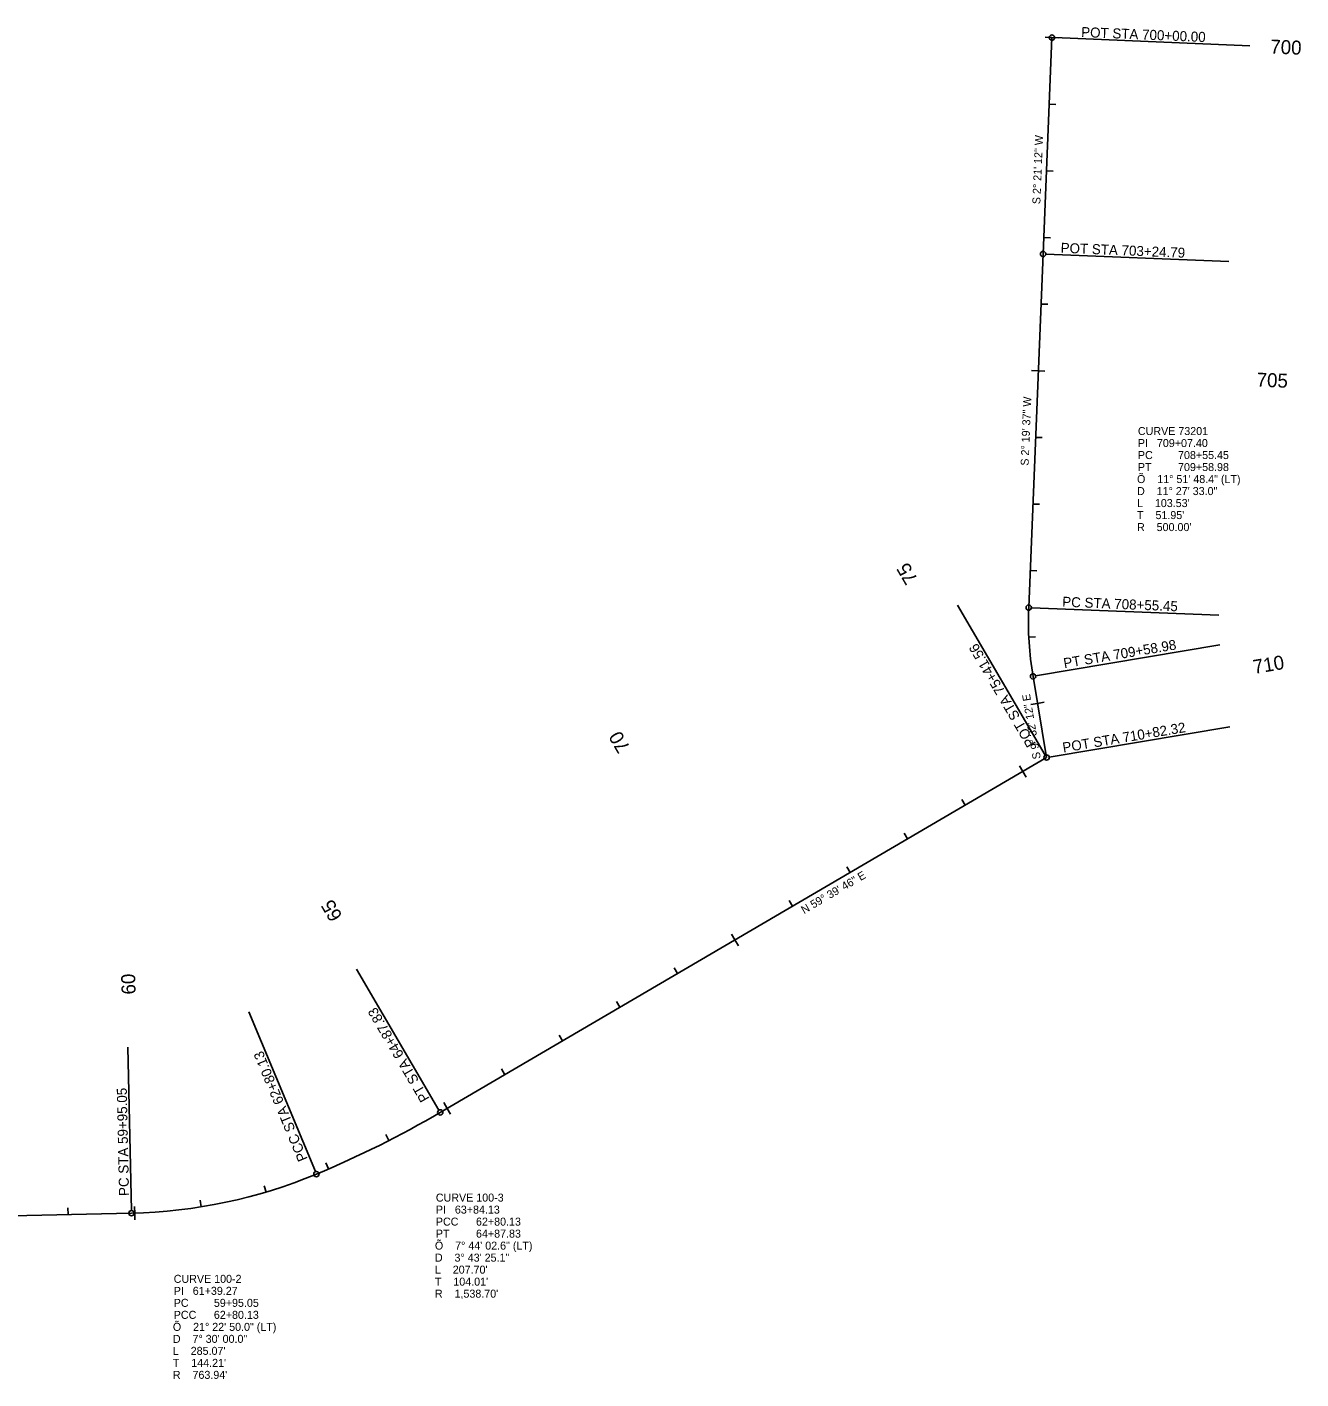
# Model space of a CAD drawing. Extents: x 2819977 to 2827606, y 113942 to 150283.
# Drawn here: x 2821906 to 2823816, y 131900 to 133927 of the extents above; entities that cross this region are included whole.
import ezdxf

# ---------------------------------------------------------------- set-up
doc = ezdxf.new("R2010")
doc.units = 0
for name, color, linetype in [('Level 63', 7, 'Continuous'), ('Roadway-Safety', 7, 'Continuous'), ('Roadway-Signs', 7, 'Continuous'), ('Roadway-Walls', 7, 'Continuous'), ('Utility-Power', 7, 'Continuous')]:
    doc.layers.add(name, color=color, linetype=linetype)

msp = doc.modelspace()

# ---------------------------------------------------------------- linework, layer by layer
at = {"layer": 'Level 63'}
msp.add_circle((2823434.8, 132831.9), 4, dxfattribs=at)
at = {"layer": 'Roadway-Safety'}
for p, q in [((2823446.8, 133911.3), (2823739.8, 133899.2)), ((2823433.4, 133586.7), (2823708, 133575.5)), ((2823432.8, 132835.4), (2823301.3, 133060.2)), ((2823411.9, 133056.5), (2823693.2, 133045.1)), ((2823418.3, 132954.2), (2823694.5, 133000.6)), ((2823438.8, 132832.6), (2823709.7, 132878.1)), ((2822523.4, 132303.1), (2822399.8, 132514.4)), ((2822338.1, 132210.9), (2822238.2, 132450.7)), ((2822062.2, 132152.7), (2822057, 132397.4))]:
    msp.add_line(p, q, dxfattribs=at)
at = {"layer": 'Utility-Power'}
for p, q in [((2823442.8, 133911.4), (2823429.5, 133586.9)), ((2823442.8, 133911.4), (2823432.8, 133911.8)), ((2823442.8, 133911.4), (2823452.8, 133911)), ((2823438.7, 133811.5), (2823448.7, 133811.1)), ((2823434.6, 133711.6), (2823444.6, 133711.2)), ((2823430.5, 133611.7), (2823440.5, 133611.3)), ((2823429.5, 133586.9), (2823407.9, 133056.7)), ((2823426.4, 133511.8), (2823436.4, 133511.4)), ((2823422.3, 133411.8), (2823412.3, 133412.2)), ((2823422.3, 133411.8), (2823432.3, 133411.4)), ((2823418.3, 133311.9), (2823428.3, 133311.5)), ((2823414.2, 133212), (2823424.2, 133211.6)), ((2823410.2, 133112.1), (2823420.1, 133111.7)), ((2823408.1, 133012.2), (2823418.1, 133012.6)), ((2823414.4, 132953.5), (2823434.8, 132831.9)), ((2823421.2, 132913.1), (2823411.3, 132911.4)), ((2823421.2, 132913.1), (2823431.1, 132914.7)), ((2822525.4, 132299.7), (2823434.8, 132831.9)), ((2823399, 132810.9), (2823393.9, 132819.6)), ((2823399, 132810.9), (2823404, 132802.3)), ((2823312.7, 132760.4), (2823307.6, 132769)), ((2823226.4, 132709.9), (2823221.3, 132718.5)), ((2823140, 132659.4), (2823135, 132668)), ((2823053.7, 132608.9), (2823048.7, 132617.5)), ((2822967.4, 132558.4), (2822962.4, 132567)), ((2822967.4, 132558.4), (2822972.5, 132549.7)), ((2822881.1, 132507.9), (2822876.1, 132516.5)), ((2822794.8, 132457.4), (2822789.8, 132466)), ((2822708.5, 132406.9), (2822703.5, 132415.5)), ((2822622.2, 132356.3), (2822617.2, 132365)), ((2822535.9, 132305.8), (2822530.8, 132314.5)), ((2822535.9, 132305.8), (2822541, 132297.2)), ((2822448.4, 132257.5), (2822443.8, 132266.4)), ((2822357.9, 132214.9), (2822353.9, 132224.1)), ((2822264.2, 132180.3), (2822261.3, 132189.9)), ((2822166.7, 132158.1), (2822165.2, 132168)), ((2821496.2, 132136.6), (2822062.3, 132148.7)), ((2821967.3, 132146.6), (2821967, 132156.6)), ((2822067.2, 132148.8), (2822067, 132158.8)), ((2822067.2, 132148.8), (2822067.5, 132138.8))]:
    msp.add_line(p, q, dxfattribs=at)
for centre in [(2823442.8, 133911.4), (2823429.5, 133586.9), (2823407.9, 133056.7), (2823414.4, 132953.5), (2823434.8, 132831.9), (2822525.4, 132299.7), (2822339.6, 132207.2), (2822062.3, 132148.7)]:
    msp.add_circle(centre, 4, dxfattribs=at)
for centre, radius, start, end in [((2823907.5, 133036.4), 500, 177.6731, 189.5366), ((2821748.2, 133627.7), 1538.7, 292.6032, 300.3373), ((2822046, 132912.4), 763.9, 271.2227, 292.6032)]:
    msp.add_arc(centre, radius, start, end, dxfattribs=at)

# ---------------------------------------------------------------- texts
at = {"layer": 'Roadway-Safety'}
for s, rotation, p in [('POT STA 700+00.00', 357.6466, (2823486.4, 133912.3)), ('POT STA 703+24.79', 357.6466, (2823455.6, 133588.8)), ('PC STA 708+55.45', 357.6731, (2823458, 133058.1)), ('POT STA 75+41.56', 120.3373, (2823419.1, 132852.8)), ('PT STA 709+58.98', 9.5366, (2823461.4, 132965.7)), ('POT STA 710+82.32', 9.5366, (2823460, 132839.2)), ('PT STA 64+87.83', 120.3373, (2822509.7, 132320.6)), ('PCC STA 62+80.13', 112.6032, (2822326.8, 132230)), ('PC STA 59+95.05', 91.2227, (2822058.7, 132174.6))]:
    msp.add_text(s, height=15, rotation=rotation, dxfattribs=at).set_placement(p)
at = {"layer": 'Roadway-Signs'}
for s, rotation, p in [('S 2%%d 21\' 12" W', 87.6466, (2823425.3, 133661.4)), ('S 2%%d 19\' 37" W', 87.6731, (2823407.7, 133269.3)), ('S 9%%d 32\' 12" E', 99.5366, (2823426.1, 132830.4)), ('N 59%%d 39\' 46" E', 30.3373, (2823071, 132597))]:
    msp.add_text(s, height=12, rotation=rotation, dxfattribs=at).set_placement(p)
at = {"layer": 'Roadway-Walls'}
for s, p in [('CURVE 73201', (2823571.7, 133315.4)), ('PI   709+07.40', (2823571.7, 133297.4)), ('PC', (2823571.7, 133279.4)), ('708+55.45', (2823631.9, 133279.4)), ('PT', (2823571.7, 133261.4)), ('709+58.98', (2823631.9, 133261.4)), ('Õ    11%%d 51\' 48.4" (LT)', (2823570.4, 133243.4)), ('D    11%%d 27\' 33.0"', (2823570.4, 133225.4)), ("T    51.95'", (2823570.4, 133189.4)), ("L    103.53'", (2823570.4, 133207.4)), ("R    500.00'", (2823570.4, 133171.4)), ('CURVE 100-3', (2822518.8, 132166)), ('PI   63+84.13', (2822518.8, 132148)), ('PCC', (2822518.8, 132130)), ('62+80.13', (2822579, 132130)), ('Õ    7%%d 44\' 02.6" (LT)', (2822517.4, 132094)), ('PT', (2822518.8, 132112)), ('64+87.83', (2822579, 132112)), ('D    3%%d 43\' 25.1"', (2822517.4, 132076)), ("L    207.70'", (2822517.4, 132058)), ('CURVE 100-2', (2822125.7, 132044.2)), ("T    104.01'", (2822517.4, 132040)), ('PI   61+39.27', (2822125.7, 132026.2)), ("R    1,538.70'", (2822517.4, 132022)), ('PC', (2822125.7, 132008.2)), ('59+95.05', (2822185.9, 132008.2)), ('Õ    21%%d 22\' 50.0" (LT)', (2822124.4, 131972.2)), ('PCC', (2822125.7, 131990.2)), ('62+80.13', (2822185.9, 131990.2)), ('D    7%%d 30\' 00.0"', (2822124.4, 131954.2)), ("L    285.07'", (2822124.4, 131936.2)), ("T    144.21'", (2822124.4, 131918.2)), ("R    763.94'", (2822124.4, 131900.2))]:
    msp.add_text(s, height=12, dxfattribs=at).set_placement(p)
at = {"layer": 'Utility-Power'}
for s, rotation, p in [(' 700', 357.6466, (2823762.1, 133887.8)), (' 705', 357.6731, (2823741.6, 133388.4)), (' 75', 120.3373, (2823246.4, 133092.4)), (' 710', 9.5366, (2823738.5, 132955.8)), (' 70', 120.3373, (2822814.9, 132839.9)), (' 65', 120.3373, (2822383.3, 132587.3)), (' 60', 91.5938, (2822068.8, 132469))]:
    msp.add_text(s, height=21, rotation=rotation, dxfattribs=at).set_placement(p)

doc.saveas('drawing.dxf')
